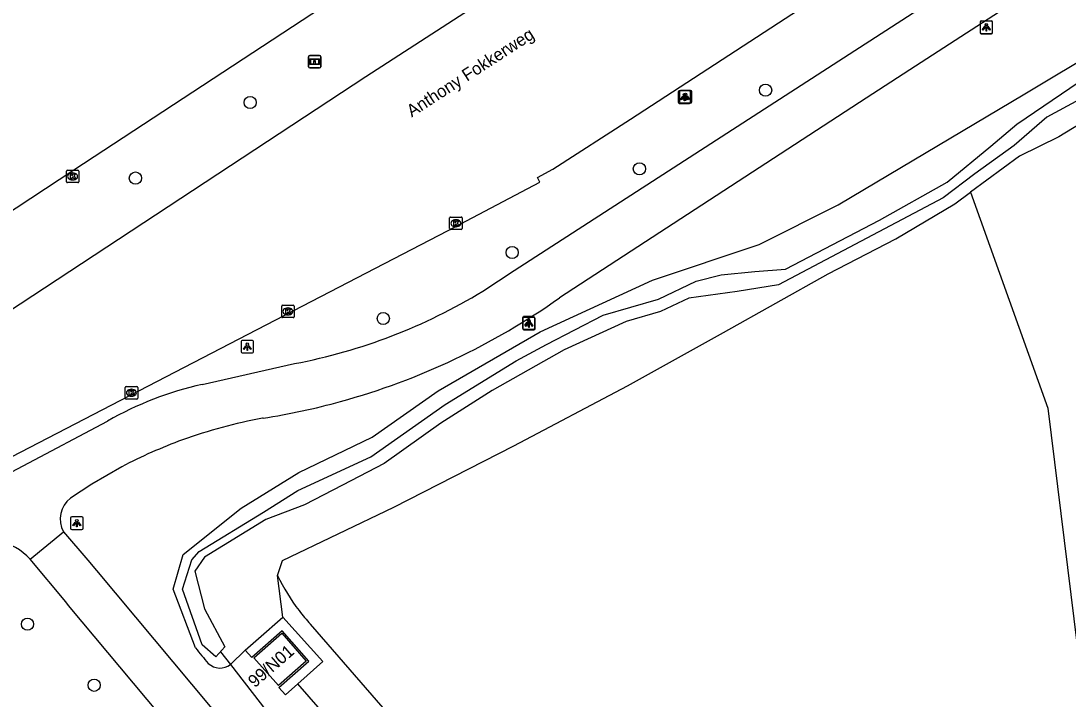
# Model space of a CAD drawing. Extents: x 156061 to 157804, y 383451 to 385640.
# Drawn here: x 156118.1 to 156202.1, y 385350 to 385404.4 of the extents above; entities that cross this region are included whole.
import ezdxf

# ---------------------------------------------------------------- set-up
doc = ezdxf.new("R2010")
doc.units = 0
for name, color, linetype in [('IMGEO_Boom', 7, 'Continuous'), ('IMGEO_Duiker', 7, 'Continuous'), ('IMGEO_Fietspad_gesloten', 7, 'Continuous'), ('IMGEO_Groenvoorziening', 7, 'Continuous'), ('IMGEO_Informatiebord', 7, 'Continuous'), ('IMGEO_Kolk', 7, 'Continuous'), ('IMGEO_Lichtpunt', 7, 'Continuous'), ('IMGEO_Loofbos', 7, 'Continuous'), ('IMGEO_Muur', 7, 'Continuous'), ('IMGEO_Openbare_ruimte_label', 7, 'Continuous'), ('IMGEO_Pand', 7, 'Continuous'), ('IMGEO_Pand_nummerreeks', 7, 'Continuous'), ('IMGEO_Rijbaan_regionaal_gesloten', 7, 'Continuous'), ('IMGEO_Waterloop', 7, 'Continuous')]:
    doc.layers.add(name, color=color, linetype=linetype)

msp = doc.modelspace()

# ---------------------------------------------------------------- linework, layer by layer
at = {"layer": 'IMGEO_Boom'}
for centre in [(156177.823, 385398.815), (156136.5, 385397.825), (156167.707, 385392.502), (156127.297, 385391.759), (156157.505, 385385.788), (156147.171, 385380.497), (156118.643, 385355.969), (156123.994, 385351.065)]:
    msp.add_circle(centre, 0.489, dxfattribs=at)
at = {"layer": 'IMGEO_Duiker'}
msp.add_lwpolyline([(156134.122, 385353.757), (156134.914, 385352.731), (156137.743, 385349.064), (156138.528, 385348.047)], dxfattribs=at)
at = {"layer": 'IMGEO_Fietspad_gesloten'}
for points in [[(156155.146, 385382.681), (156157.663, 385384.331), (156254.836, 385447.18), (156339.618, 385502.15), (156356.83, 385513.33), (156358.414, 385514.308), (156361.437, 385516.314), (156364.237, 385517.925), (156365.932, 385518.78), (156366.793, 385519.182), (156370.191, 385520.476)], [(156376.455, 385518.834), (156375.615, 385518.519), (156373.73, 385517.992), (156368.945, 385515.977), (156366.209, 385514.717), (156363.43, 385513.21), (156271.295, 385453.508), (156267.347, 385450.95), (156189.391, 385400.452), (156185.888, 385398.17), (156161.305, 385382.155)], [(156132.641, 385375.197), (156140.061, 385376.875)], [(156097.829, 385357.837), (156097.994, 385357.927), (156125.069, 385372.264)], [(156137.531, 385372.49), (156137.499, 385372.485)], [(156126.209, 385368.594), (156123.812, 385367.192), (156122.086, 385366.08)], [(156118.856, 385361.174), (156121.522, 385363.38)], [(156121.522, 385363.38), (156123.473, 385361.108), (156124.171, 385360.272), (156151.782, 385327.202)], [(156177.328, 385291.209), (156121.942, 385357.471), (156121.706, 385357.754), (156118.856, 385361.174)]]:
    msp.add_lwpolyline(points, dxfattribs=at)
for centre, radius, start, end in [((156131.607, 385421.339), 45.261, 280.765, 301.337), ((156128.803, 385428.032), 56.223, 285.41406, 305.31588), ((156138.572, 385348.643), 27.208, 102.59183, 119.75573), ((156128.815, 385427.969), 56.159, 278.92846, 285.41963), ((156144.397, 385334.134), 38.966, 100.19662, 109.99344), ((156144.386, 385334.178), 38.921, 110.00054, 117.84136), ((156123.412, 385364.394), 2.145, 128.18771, 208.2147), ((156115.576, 385358.305), 4.358, 41.16871, 119.45122)]:
    msp.add_arc(centre, radius, start, end, dxfattribs=at)
at = {"layer": 'IMGEO_Groenvoorziening'}
for points in [[(156132.124, 385354.072), (156130.332, 385358.77), (156131.122, 385361.565), (156135.769, 385365.262), (156140.41, 385368.141), (156146.274, 385370.967), (156151.561, 385374.676), (156159.748, 385379.429), (156168.749, 385383.564), (156177.32, 385386.43), (156183.649, 385389.607), (156198.621, 385398.528), (156229.223, 385416.905), (156256.324, 385433.029), (156278.013, 385445.947), (156292.411, 385454.179), (156297.741, 385457.946), (156299.672, 385458.497), (156300.122, 385458.006), (156300.518, 385457.573), (156299.547, 385455.995), (156298.761, 385455.011), (156297.274, 385454.136), (156283.451, 385445.592)], [(156139.112, 385356.54), (156138.687, 385359.878)], [(156136.104, 385353.881), (156134.914, 385352.731)], [(156309.519, 385180.688), (156292.679, 385186.81), (156275.143, 385200.293), (156253.968, 385221.655), (156247.683, 385227.995), (156228.502, 385250), (156140.316, 385351.172)]]:
    msp.add_lwpolyline(points, dxfattribs=at)
for centre, radius, start, end in [((156145.275, 385363.705), 16.302, 216.22196, 221.88639), ((156134.079, 385353.813), 1.366, 226.53175, 307.66295)]:
    msp.add_arc(centre, radius, start, end, dxfattribs=at)
at = {"layer": 'IMGEO_Informatiebord'}
for p, q in [((156141.27, 385401.593), (156142.06, 385401.593)), ((156142.06, 385401.593), (156141.27, 385401.593)), ((156141.17, 385400.693), (156141.17, 385401.493)), ((156141.17, 385401.493), (156141.17, 385400.693)), ((156142.16, 385401.493), (156142.16, 385400.693)), ((156142.16, 385400.693), (156142.16, 385401.493)), ((156142.06, 385400.593), (156141.27, 385400.593)), ((156141.27, 385400.593), (156142.06, 385400.593))]:
    msp.add_line(p, q, dxfattribs=at)
for points in [[(156141.271, 385401.325), (156142.059, 385401.325), (156142.059, 385400.861), (156141.271, 385400.861), (156141.271, 385401.325)], [(156141.336, 385401.26), (156141.336, 385400.926), (156141.611, 385400.926), (156141.612, 385401.139), (156141.716, 385401.14), (156141.717, 385400.926), (156141.994, 385400.926), (156141.994, 385401.26), (156141.718, 385401.26), (156141.718, 385401.18), (156141.612, 385401.18), (156141.612, 385401.26), (156141.336, 385401.26)]]:
    msp.add_lwpolyline(points, dxfattribs=at)
for centre, start, end in [((156141.27, 385401.493), 90, 180), ((156141.27, 385401.493), 90, 180), ((156142.06, 385401.493), 0, 90), ((156142.06, 385401.493), 360, 90), ((156141.27, 385400.693), 180, 270), ((156141.27, 385400.693), 180, 270), ((156142.06, 385400.693), 270, 0), ((156142.06, 385400.693), 270, 0)]:
    msp.add_arc(centre, 0.1, start, end, dxfattribs=at)
at = {"layer": 'IMGEO_Kolk'}
for p, q in [((156121.839, 385392.392), (156122.691, 385392.392)), ((156121.764, 385391.466), (156121.764, 385392.318)), ((156122.275, 385391.612), (156122.25, 385391.612)), ((156122.252, 385392.172), (156122.277, 385392.172)), ((156122.765, 385392.318), (156122.765, 385391.466)), ((156122.691, 385391.392), (156121.839, 385391.392)), ((156152.493, 385387.705), (156152.493, 385388.557)), ((156152.568, 385388.631), (156153.42, 385388.631)), ((156152.981, 385388.411), (156153.006, 385388.411)), ((156153.494, 385388.557), (156153.494, 385387.705)), ((156153.42, 385387.631), (156152.568, 385387.631)), ((156153.004, 385387.851), (156152.979, 385387.851)), ((156139.025, 385380.636), (156139.025, 385381.488)), ((156139.1, 385381.562), (156139.952, 385381.562)), ((156140.026, 385381.488), (156140.026, 385380.636)), ((156139.536, 385380.782), (156139.511, 385380.782)), ((156139.513, 385381.342), (156139.538, 385381.342)), ((156139.952, 385380.562), (156139.1, 385380.562)), ((156126.476, 385374.106), (156126.476, 385374.958)), ((156126.551, 385375.032), (156127.403, 385375.032)), ((156126.964, 385374.812), (156126.989, 385374.812)), ((156127.477, 385374.958), (156127.477, 385374.106)), ((156127.403, 385374.032), (156126.551, 385374.032)), ((156126.987, 385374.252), (156126.962, 385374.252))]:
    msp.add_line(p, q, dxfattribs=at)
for points in [[(156121.839, 385392.392), (156122.691, 385392.392)], [(156121.764, 385391.466), (156121.764, 385392.318)], [(156122.085, 385392.092), (156122.208, 385392.092), (156122.208, 385391.941), (156122.338, 385392.092), (156122.502, 385392.092), (156122.356, 385391.941), (156122.509, 385391.692), (156122.357, 385391.692), (156122.272, 385391.856), (156122.208, 385391.789), (156122.208, 385391.692), (156122.085, 385391.692), (156122.085, 385392.092)], [(156122.765, 385392.318), (156122.765, 385391.466)], [(156122.691, 385391.392), (156121.839, 385391.392)], [(156152.493, 385387.705), (156152.493, 385388.557)], [(156152.568, 385388.631), (156153.42, 385388.631)], [(156152.814, 385388.331), (156152.937, 385388.331), (156152.937, 385388.18), (156153.067, 385388.331), (156153.231, 385388.331), (156153.085, 385388.18), (156153.238, 385387.931), (156153.086, 385387.931), (156153.001, 385388.095), (156152.937, 385388.028), (156152.937, 385387.931), (156152.814, 385387.931), (156152.814, 385388.331)], [(156153.494, 385388.557), (156153.494, 385387.705)], [(156153.42, 385387.631), (156152.568, 385387.631)], [(156139.025, 385380.636), (156139.025, 385381.488)], [(156139.1, 385381.562), (156139.952, 385381.562)], [(156140.026, 385381.488), (156140.026, 385380.636)], [(156139.346, 385381.262), (156139.469, 385381.262), (156139.469, 385381.111), (156139.599, 385381.262), (156139.763, 385381.262), (156139.617, 385381.111), (156139.77, 385380.862), (156139.618, 385380.862), (156139.533, 385381.026), (156139.469, 385380.959), (156139.469, 385380.862), (156139.346, 385380.862), (156139.346, 385381.262)], [(156139.952, 385380.562), (156139.1, 385380.562)], [(156126.476, 385374.106), (156126.476, 385374.958)], [(156126.551, 385375.032), (156127.403, 385375.032)], [(156126.797, 385374.732), (156126.92, 385374.732), (156126.92, 385374.581), (156127.05, 385374.732), (156127.214, 385374.732), (156127.068, 385374.581), (156127.221, 385374.332), (156127.069, 385374.332), (156126.984, 385374.496), (156126.92, 385374.429), (156126.92, 385374.332), (156126.797, 385374.332), (156126.797, 385374.732)], [(156127.477, 385374.958), (156127.477, 385374.106)], [(156127.403, 385374.032), (156126.551, 385374.032)]]:
    msp.add_lwpolyline(points, dxfattribs=at)
for centre, start, end in [((156121.841, 385392.316), 91.55205, 178.44795), ((156121.841, 385392.316), 91.55205, 178.44795), ((156122.689, 385392.316), 1.55205, 88.44795), ((156122.689, 385392.316), 1.55205, 88.44795), ((156121.841, 385391.468), 181.55205, 268.44795), ((156121.841, 385391.468), 181.55205, 268.44795), ((156122.689, 385391.468), 271.55205, 358.44795), ((156122.689, 385391.468), 271.55205, 358.44795), ((156152.57, 385388.555), 91.55205, 178.44795), ((156152.57, 385388.555), 91.55205, 178.44795), ((156153.418, 385388.555), 1.55205, 88.44795), ((156153.418, 385388.555), 1.55205, 88.44795), ((156152.57, 385387.707), 181.55205, 268.44795), ((156152.57, 385387.707), 181.55205, 268.44795), ((156153.418, 385387.707), 271.55205, 358.44795), ((156153.418, 385387.707), 271.55205, 358.44795), ((156139.102, 385381.486), 91.55205, 178.44795), ((156139.102, 385381.486), 91.55205, 178.44795), ((156139.95, 385381.486), 1.55205, 88.44795), ((156139.95, 385381.486), 1.55205, 88.44795), ((156139.102, 385380.638), 181.55205, 268.44795), ((156139.102, 385380.638), 181.55205, 268.44795), ((156139.95, 385380.638), 271.55205, 358.44795), ((156139.95, 385380.638), 271.55205, 358.44795), ((156126.553, 385374.956), 91.55205, 178.44795), ((156126.553, 385374.956), 91.55205, 178.44795), ((156127.401, 385374.956), 1.55205, 88.44795), ((156127.401, 385374.956), 1.55205, 88.44795), ((156126.553, 385374.108), 181.55205, 268.44795), ((156126.553, 385374.108), 181.55205, 268.44795), ((156127.401, 385374.108), 271.55205, 358.44795), ((156127.401, 385374.108), 271.55205, 358.44795)]:
    msp.add_arc(centre, 0.0765, start, end, dxfattribs=at)
for centre, major_axis, ratio, start_param, end_param in [((156122.251, 385391.892), (-0.387, 0.002), 0.722429, 4.712389, 7.853982), ((156122.276, 385391.892), (-0.39, 0.002), 0.717154, 1.570796, 4.712389), ((156152.98, 385388.131), (-0.387, 0.002), 0.722429, 4.712389, 7.853982), ((156153.005, 385388.131), (-0.39, 0.002), 0.717154, 1.570796, 4.712389), ((156139.512, 385381.062), (-0.387, 0.002), 0.722429, 4.712389, 7.853982), ((156139.537, 385381.062), (-0.39, 0.002), 0.717154, 1.570796, 4.712389), ((156126.963, 385374.532), (-0.387, 0.002), 0.722429, 4.712389, 7.853982), ((156126.988, 385374.532), (-0.39, 0.002), 0.717154, 1.570796, 4.712389)]:
    msp.add_ellipse(centre, major_axis=major_axis, ratio=ratio, start_param=start_param, end_param=end_param, dxfattribs=at)
at = {"layer": 'IMGEO_Lichtpunt'}
for p, q in [((156195.021, 385404.273), (156195.021, 385403.466)), ((156195.021, 385404.273), (156195.021, 385403.466)), ((156195.024, 385404.241), (156195.024, 385403.434)), ((156195.024, 385404.241), (156195.024, 385403.434)), ((156195.926, 385404.336), (156195.118, 385404.336)), ((156195.926, 385404.336), (156195.118, 385404.336)), ((156196.017, 385403.466), (156196.017, 385404.273)), ((156196.017, 385403.466), (156196.017, 385404.273)), ((156196.02, 385403.434), (156196.02, 385404.241)), ((156196.02, 385403.434), (156196.02, 385404.241)), ((156195.115, 385403.372), (156195.923, 385403.372)), ((156195.115, 385403.372), (156195.923, 385403.372)), ((156195.118, 385403.34), (156195.926, 385403.34)), ((156195.118, 385403.34), (156195.926, 385403.34)), ((156170.811, 385398.657), (156170.811, 385397.85)), ((156170.811, 385398.657), (156170.811, 385397.85)), ((156171.713, 385398.752), (156170.905, 385398.752)), ((156171.713, 385398.752), (156170.905, 385398.752)), ((156170.914, 385398.684), (156170.914, 385397.877)), ((156170.914, 385398.684), (156170.914, 385397.877)), ((156171.816, 385398.779), (156171.008, 385398.779)), ((156171.816, 385398.779), (156171.008, 385398.779)), ((156171.807, 385397.85), (156171.807, 385398.657)), ((156171.807, 385397.85), (156171.807, 385398.657)), ((156171.91, 385397.877), (156171.91, 385398.684)), ((156171.91, 385397.877), (156171.91, 385398.684)), ((156170.905, 385397.756), (156171.713, 385397.756)), ((156170.905, 385397.756), (156171.713, 385397.756)), ((156171.008, 385397.783), (156171.816, 385397.783)), ((156171.008, 385397.783), (156171.816, 385397.783)), ((156159.224, 385380.639), (156158.416, 385380.639)), ((156159.224, 385380.639), (156158.416, 385380.639)), ((156158.322, 385380.544), (156158.322, 385379.737)), ((156158.322, 385380.544), (156158.322, 385379.737)), ((156158.353, 385380.483), (156158.353, 385379.676)), ((156158.353, 385380.483), (156158.353, 385379.676)), ((156159.255, 385380.578), (156158.447, 385380.578)), ((156159.255, 385380.578), (156158.447, 385380.578)), ((156159.318, 385379.737), (156159.318, 385380.544)), ((156159.318, 385379.737), (156159.318, 385380.544)), ((156159.349, 385379.676), (156159.349, 385380.483)), ((156159.349, 385379.676), (156159.349, 385380.483)), ((156158.416, 385379.643), (156159.224, 385379.643)), ((156158.416, 385379.643), (156159.224, 385379.643)), ((156158.447, 385379.582), (156159.255, 385379.582)), ((156158.447, 385379.582), (156159.255, 385379.582)), ((156135.77, 385378.636), (156135.77, 385377.829)), ((156135.77, 385378.636), (156135.77, 385377.829)), ((156136.672, 385378.731), (156135.864, 385378.731)), ((156136.672, 385378.731), (156135.864, 385378.731)), ((156136.766, 385377.829), (156136.766, 385378.636)), ((156136.766, 385377.829), (156136.766, 385378.636)), ((156135.864, 385377.735), (156136.672, 385377.735)), ((156135.864, 385377.735), (156136.672, 385377.735)), ((156122.1, 385364.475), (156122.1, 385363.668)), ((156122.1, 385364.475), (156122.1, 385363.668)), ((156123.002, 385364.57), (156122.194, 385364.57)), ((156123.002, 385364.57), (156122.194, 385364.57)), ((156123.096, 385363.668), (156123.096, 385364.475)), ((156123.096, 385363.668), (156123.096, 385364.475)), ((156122.194, 385363.574), (156123.002, 385363.574)), ((156122.194, 385363.574), (156123.002, 385363.574))]:
    msp.add_line(p, q, dxfattribs=at)
for points in [[(156195.395, 385403.937), (156195.434, 385403.909), (156195.246, 385403.647), (156195.208, 385403.674), (156195.395, 385403.937)], [(156195.398, 385403.905), (156195.437, 385403.877), (156195.249, 385403.615), (156195.211, 385403.642), (156195.398, 385403.905)], [(156195.497, 385403.889), (156195.544, 385403.889), (156195.544, 385403.567), (156195.497, 385403.567), (156195.497, 385403.889)], [(156195.5, 385403.857), (156195.547, 385403.857), (156195.547, 385403.535), (156195.5, 385403.535), (156195.5, 385403.857)], [(156195.607, 385403.909), (156195.645, 385403.936), (156195.832, 385403.674), (156195.793, 385403.646), (156195.607, 385403.909)], [(156195.61, 385403.877), (156195.648, 385403.904), (156195.835, 385403.642), (156195.796, 385403.614), (156195.61, 385403.877)], [(156171.185, 385398.321), (156171.224, 385398.293), (156171.036, 385398.031), (156170.998, 385398.058), (156171.185, 385398.321)], [(156171.288, 385398.348), (156171.327, 385398.32), (156171.139, 385398.058), (156171.101, 385398.085), (156171.288, 385398.348)], [(156171.287, 385398.273), (156171.334, 385398.273), (156171.334, 385397.951), (156171.287, 385397.951), (156171.287, 385398.273)], [(156171.39, 385398.3), (156171.437, 385398.3), (156171.437, 385397.978), (156171.39, 385397.978), (156171.39, 385398.3)], [(156171.397, 385398.293), (156171.435, 385398.32), (156171.622, 385398.058), (156171.583, 385398.03), (156171.397, 385398.293)], [(156171.5, 385398.32), (156171.538, 385398.347), (156171.725, 385398.085), (156171.686, 385398.057), (156171.5, 385398.32)], [(156158.696, 385380.208), (156158.735, 385380.18), (156158.547, 385379.918), (156158.509, 385379.945), (156158.696, 385380.208)], [(156158.727, 385380.147), (156158.766, 385380.119), (156158.578, 385379.857), (156158.54, 385379.884), (156158.727, 385380.147)], [(156158.798, 385380.16), (156158.845, 385380.16), (156158.845, 385379.838), (156158.798, 385379.838), (156158.798, 385380.16)], [(156158.829, 385380.099), (156158.876, 385380.099), (156158.876, 385379.777), (156158.829, 385379.777), (156158.829, 385380.099)], [(156158.908, 385380.18), (156158.946, 385380.207), (156159.133, 385379.945), (156159.094, 385379.917), (156158.908, 385380.18)], [(156158.939, 385380.119), (156158.977, 385380.146), (156159.164, 385379.884), (156159.125, 385379.856), (156158.939, 385380.119)], [(156136.144, 385378.3), (156136.183, 385378.272), (156135.995, 385378.01), (156135.957, 385378.037), (156136.144, 385378.3)], [(156136.246, 385378.252), (156136.293, 385378.252), (156136.293, 385377.93), (156136.246, 385377.93), (156136.246, 385378.252)], [(156136.356, 385378.272), (156136.394, 385378.299), (156136.581, 385378.037), (156136.542, 385378.009), (156136.356, 385378.272)], [(156122.474, 385364.139), (156122.513, 385364.111), (156122.325, 385363.849), (156122.287, 385363.876), (156122.474, 385364.139)], [(156122.576, 385364.091), (156122.623, 385364.091), (156122.623, 385363.769), (156122.576, 385363.769), (156122.576, 385364.091)], [(156122.686, 385364.111), (156122.724, 385364.138), (156122.911, 385363.876), (156122.872, 385363.848), (156122.686, 385364.111)]]:
    msp.add_lwpolyline(points, dxfattribs=at)
for centre in [(156195.52, 385404.071), (156195.523, 385404.039), (156171.31, 385398.455), (156171.413, 385398.482), (156158.821, 385380.342), (156158.852, 385380.281), (156136.269, 385378.434), (156122.599, 385364.273)]:
    msp.add_circle(centre, 0.0994, dxfattribs=at)
for centre, start, end in [((156195.115, 385404.273), 90, 180), ((156195.115, 385404.273), 90, 180), ((156195.118, 385404.241), 90, 180), ((156195.118, 385404.241), 90, 180), ((156195.923, 385404.273), 0, 90), ((156195.923, 385404.273), 0, 90), ((156195.926, 385404.241), 0, 90), ((156195.926, 385404.241), 0, 90), ((156195.115, 385403.466), 180, 270), ((156195.115, 385403.466), 180, 270), ((156195.118, 385403.434), 180, 270), ((156195.118, 385403.434), 180, 270), ((156195.923, 385403.466), 270, 0), ((156195.923, 385403.466), 270, 360), ((156195.926, 385403.434), 270, 0), ((156195.926, 385403.434), 270, 360), ((156170.905, 385398.657), 90, 180), ((156170.905, 385398.657), 90, 180), ((156171.008, 385398.684), 90, 180), ((156171.008, 385398.684), 90, 180), ((156171.713, 385398.657), 0, 90), ((156171.713, 385398.657), 0, 90), ((156171.816, 385398.684), 0, 90), ((156171.816, 385398.684), 0, 90), ((156170.905, 385397.85), 180, 270), ((156170.905, 385397.85), 180, 270), ((156171.008, 385397.877), 180, 270), ((156171.008, 385397.877), 180, 270), ((156171.713, 385397.85), 270, 0), ((156171.713, 385397.85), 270, 360), ((156171.816, 385397.877), 270, 0), ((156171.816, 385397.877), 270, 360), ((156158.416, 385380.544), 90, 180), ((156158.416, 385380.544), 90, 180), ((156159.224, 385380.544), 0, 90), ((156159.224, 385380.544), 0, 90), ((156158.447, 385380.483), 90, 180), ((156158.447, 385380.483), 90, 180), ((156159.255, 385380.483), 0, 90), ((156159.255, 385380.483), 0, 90), ((156158.416, 385379.737), 180, 270), ((156158.416, 385379.737), 180, 270), ((156158.447, 385379.676), 180, 270), ((156158.447, 385379.676), 180, 270), ((156159.224, 385379.737), 270, 0), ((156159.224, 385379.737), 270, 360), ((156159.255, 385379.676), 270, 0), ((156159.255, 385379.676), 270, 360), ((156135.864, 385378.636), 90, 180), ((156135.864, 385378.636), 90, 180), ((156136.672, 385378.636), 0, 90), ((156136.672, 385378.636), 0, 90), ((156135.864, 385377.829), 180, 270), ((156135.864, 385377.829), 180, 270), ((156136.672, 385377.829), 270, 0), ((156136.672, 385377.829), 270, 360), ((156122.194, 385364.475), 90, 180), ((156122.194, 385364.475), 90, 180), ((156123.002, 385364.475), 0, 90), ((156123.002, 385364.475), 0, 90), ((156122.194, 385363.668), 180, 270), ((156122.194, 385363.668), 180, 270), ((156123.002, 385363.668), 270, 0), ((156123.002, 385363.668), 270, 360)]:
    msp.add_arc(centre, 0.0946, start, end, dxfattribs=at)
at = {"layer": 'IMGEO_Loofbos'}
for points in [[(156283.451, 385445.592), (156231.175, 385413.278), (156201.341, 385395.08), (156198.192, 385393.505), (156194.259, 385390.622)], [(156138.687, 385359.878), (156139.092, 385361.079), (156148.016, 385365.366), (156157.64, 385370.266), (156166.739, 385375.078), (156174.438, 385379.365), (156182.837, 385384.089), (156188.262, 385386.889), (156192.986, 385389.689), (156194.259, 385390.622)], [(156194.259, 385390.622), (156200.466, 385373.294), (156207.265, 385318.028), (156209.431, 385312.369), (156244.765, 385266.89), (156273.471, 385237.156), (156322.018, 385207.14)], [(156309.519, 385180.688), (156293.366, 385188.187), (156275.563, 385201.731), (156250.074, 385230.682), (156233.307, 385250), (156141.333, 385355.967)]]:
    msp.add_lwpolyline(points, dxfattribs=at)
for centre, radius, start, end in [((156153.941, 385367.252), 16.943, 205.79963, 217.02343), ((156153.76, 385367.443), 16.915, 217.91063, 222.72317)]:
    msp.add_arc(centre, radius, start, end, dxfattribs=at)
at = {"layer": 'IMGEO_Muur'}
for points in [[(156136.104, 385353.881), (156137.153, 385354.808), (156139.112, 385356.54)], [(156139.112, 385356.54), (156142.328, 385352.959), (156140.316, 385351.172)], [(156140.316, 385351.172), (156139.329, 385350.295), (156138.808, 385350.896), (156141.213, 385353.008), (156139.055, 385355.418), (156136.634, 385353.281), (156136.104, 385353.881)]]:
    msp.add_lwpolyline(points, dxfattribs=at)
at = {"layer": 'IMGEO_Pand'}
msp.add_lwpolyline([(156140.985, 385352.992), (156138.774, 385351.041), (156136.784, 385353.269), (156139.027, 385355.243), (156140.985, 385352.992)], dxfattribs=at)
at = {"layer": 'IMGEO_Rijbaan_regionaal_gesloten'}
for points in [[(156089.022, 385370.466), (156122.362, 385392.42), (156146.252, 385408.111), (156195.471, 385439.961), (156213.93, 385451.914), (156215.231, 385452.756), (156243.156, 385469.509), (156254.776, 385476.357), (156266.946, 385483.554), (156278.515, 385490.498), (156290.492, 385497.867), (156302.474, 385505.405), (156314.1, 385512.838), (156346.089, 385533.559)], [(156093.268, 385365.389), (156145.76, 385399.909), (156224.676, 385450.976), (156281.687, 385487.986), (156347.87, 385530.832)], [(156097.829, 385357.837), (156097.06, 385358.974), (156100.569, 385360.692), (156152.382, 385387.554), (156159.731, 385391.428), (156159.544, 385391.815), (156160.762, 385392.485), (156166.982, 385396.482), (156253.2, 385452.656), (156304.354, 385485.797), (156304.543, 385485.405), (156333.022, 385500.076), (156355.546, 385514.471), (156357.592, 385515.726)]]:
    msp.add_lwpolyline(points, dxfattribs=at)
at = {"layer": 'IMGEO_Waterloop'}
for points in [[(156207.947, 385400.745), (156200.379, 385396.655), (156197.754, 385394.38), (156194.605, 385392.105), (156192.067, 385390.181), (156178.856, 385383.181), (156175.532, 385382.657), (156171.682, 385382.132), (156169.393, 385381.057)], [(156169.393, 385381.057), (156166.652, 385380.24), (156161.665, 385377.965), (156155.89, 385374.728), (156151.778, 385372.103), (156147.229, 385368.866), (156143.904, 385367.116), (156140.842, 385365.541), (156137.763, 385364.363), (156132.846, 385361.334), (156132.071, 385360.226), (156132.837, 385357.208), (156134.477, 385354.146), (156133.734, 385353.336), (156132.64, 385354.321), (156131.065, 385358.761), (156131.809, 385361.123), (156132.395, 385361.805), (156137.577, 385364.943), (156140.317, 385366.679), (156146.179, 385369.391), (156152.128, 385373.59), (156157.815, 385377.09), (156160.265, 385378.402), (156164.814, 385380.765), (156169.239, 385382.049), (156172.251, 385383.477), (156174.263, 385384.002), (156176.975, 385384.264), (156179.425, 385384.439), (156186.949, 385388.376), (156192.374, 385391.438), (156195.873, 385394.325), (156197.973, 385396.075), (156202.96, 385399.487)]]:
    msp.add_lwpolyline(points, dxfattribs=at)

# ---------------------------------------------------------------- texts
at = {"layer": 'IMGEO_Openbare_ruimte_label'}
msp.add_text('Anthony Fokkerweg', height=1, rotation=32.95901, dxfattribs=at).set_placement((156149.456, 385396.61))
at = {"layer": 'IMGEO_Pand_nummerreeks'}
msp.add_text('99/N01', height=1, rotation=40.99178, dxfattribs=at).set_placement((156136.864, 385350.819))

doc.saveas('drawing.dxf')
